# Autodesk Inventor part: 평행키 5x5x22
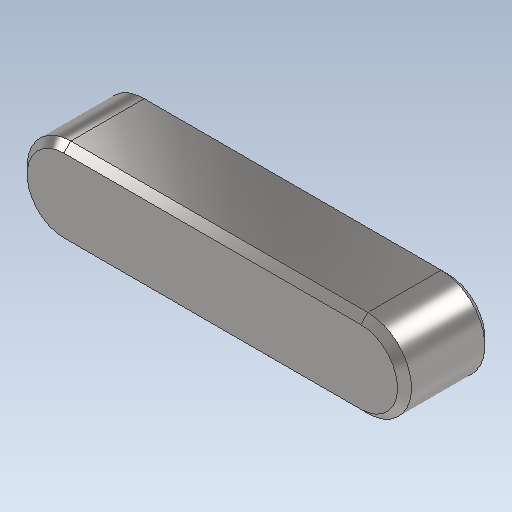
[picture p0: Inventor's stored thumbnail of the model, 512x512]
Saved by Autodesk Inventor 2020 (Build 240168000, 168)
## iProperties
Created: 2024-09
Part Number: 평행키 5x5x22
Material: 강철, 연강
Description: 키 및 해당 키홈
Document SubType Name: Modeling
Designer: oem
Density: 7.85 g/cm^3
Appearance: 기본값
Author: jhkim
Sending System: Autodesk Inventor 2025
Preprocessor: ST-DEVELOPER v20
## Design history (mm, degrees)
feature "Solid1"
node "솔리드1"
